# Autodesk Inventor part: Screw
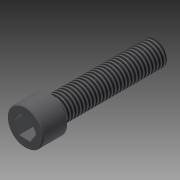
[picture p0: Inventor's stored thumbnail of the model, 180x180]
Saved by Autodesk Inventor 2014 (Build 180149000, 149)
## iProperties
Created: 2006-07
Part Number: Screw
Material: system_material_0
Description: SCREW, CAP, 1/4-20 X 3/8
Document SubType Name: Modeling
Designer: Z.MCGILL
Engineer: SAP
Manufacturer: Standard
Standards Organization: Custom
Mass: 26.2447 g
Surface Area: 18.9522 cm^2
Volume: 3.34682 cm^3
Density: 7.84168 g/cm^3
Appearance: system_RenderingStyle_0
NetWeight: 0.005
WeightUOM: KG
ModelCode: Comp
Author: Z.MCGILL
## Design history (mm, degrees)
node "SHCS"
body "Solid1"
tag "TaggingFeature2"
feature "DerivedBody::SHCS"
other parameters: "Thread_Length" = 69.85, "Head_Chamfer" = 0.635, "Thread_Chamfer" = 0.2286, "Thread_Diameter" = 15.875, "Head_Diameter" = 23.8252, "Head_Length" = 15.875, "Hex_Head_Width" = 12.7, "Hex_Head_Depth" = 12.7, "d23" = 0, "d24" = 0
